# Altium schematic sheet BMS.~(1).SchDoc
size A3; SheetNumber: 3; SheetTotal: 3
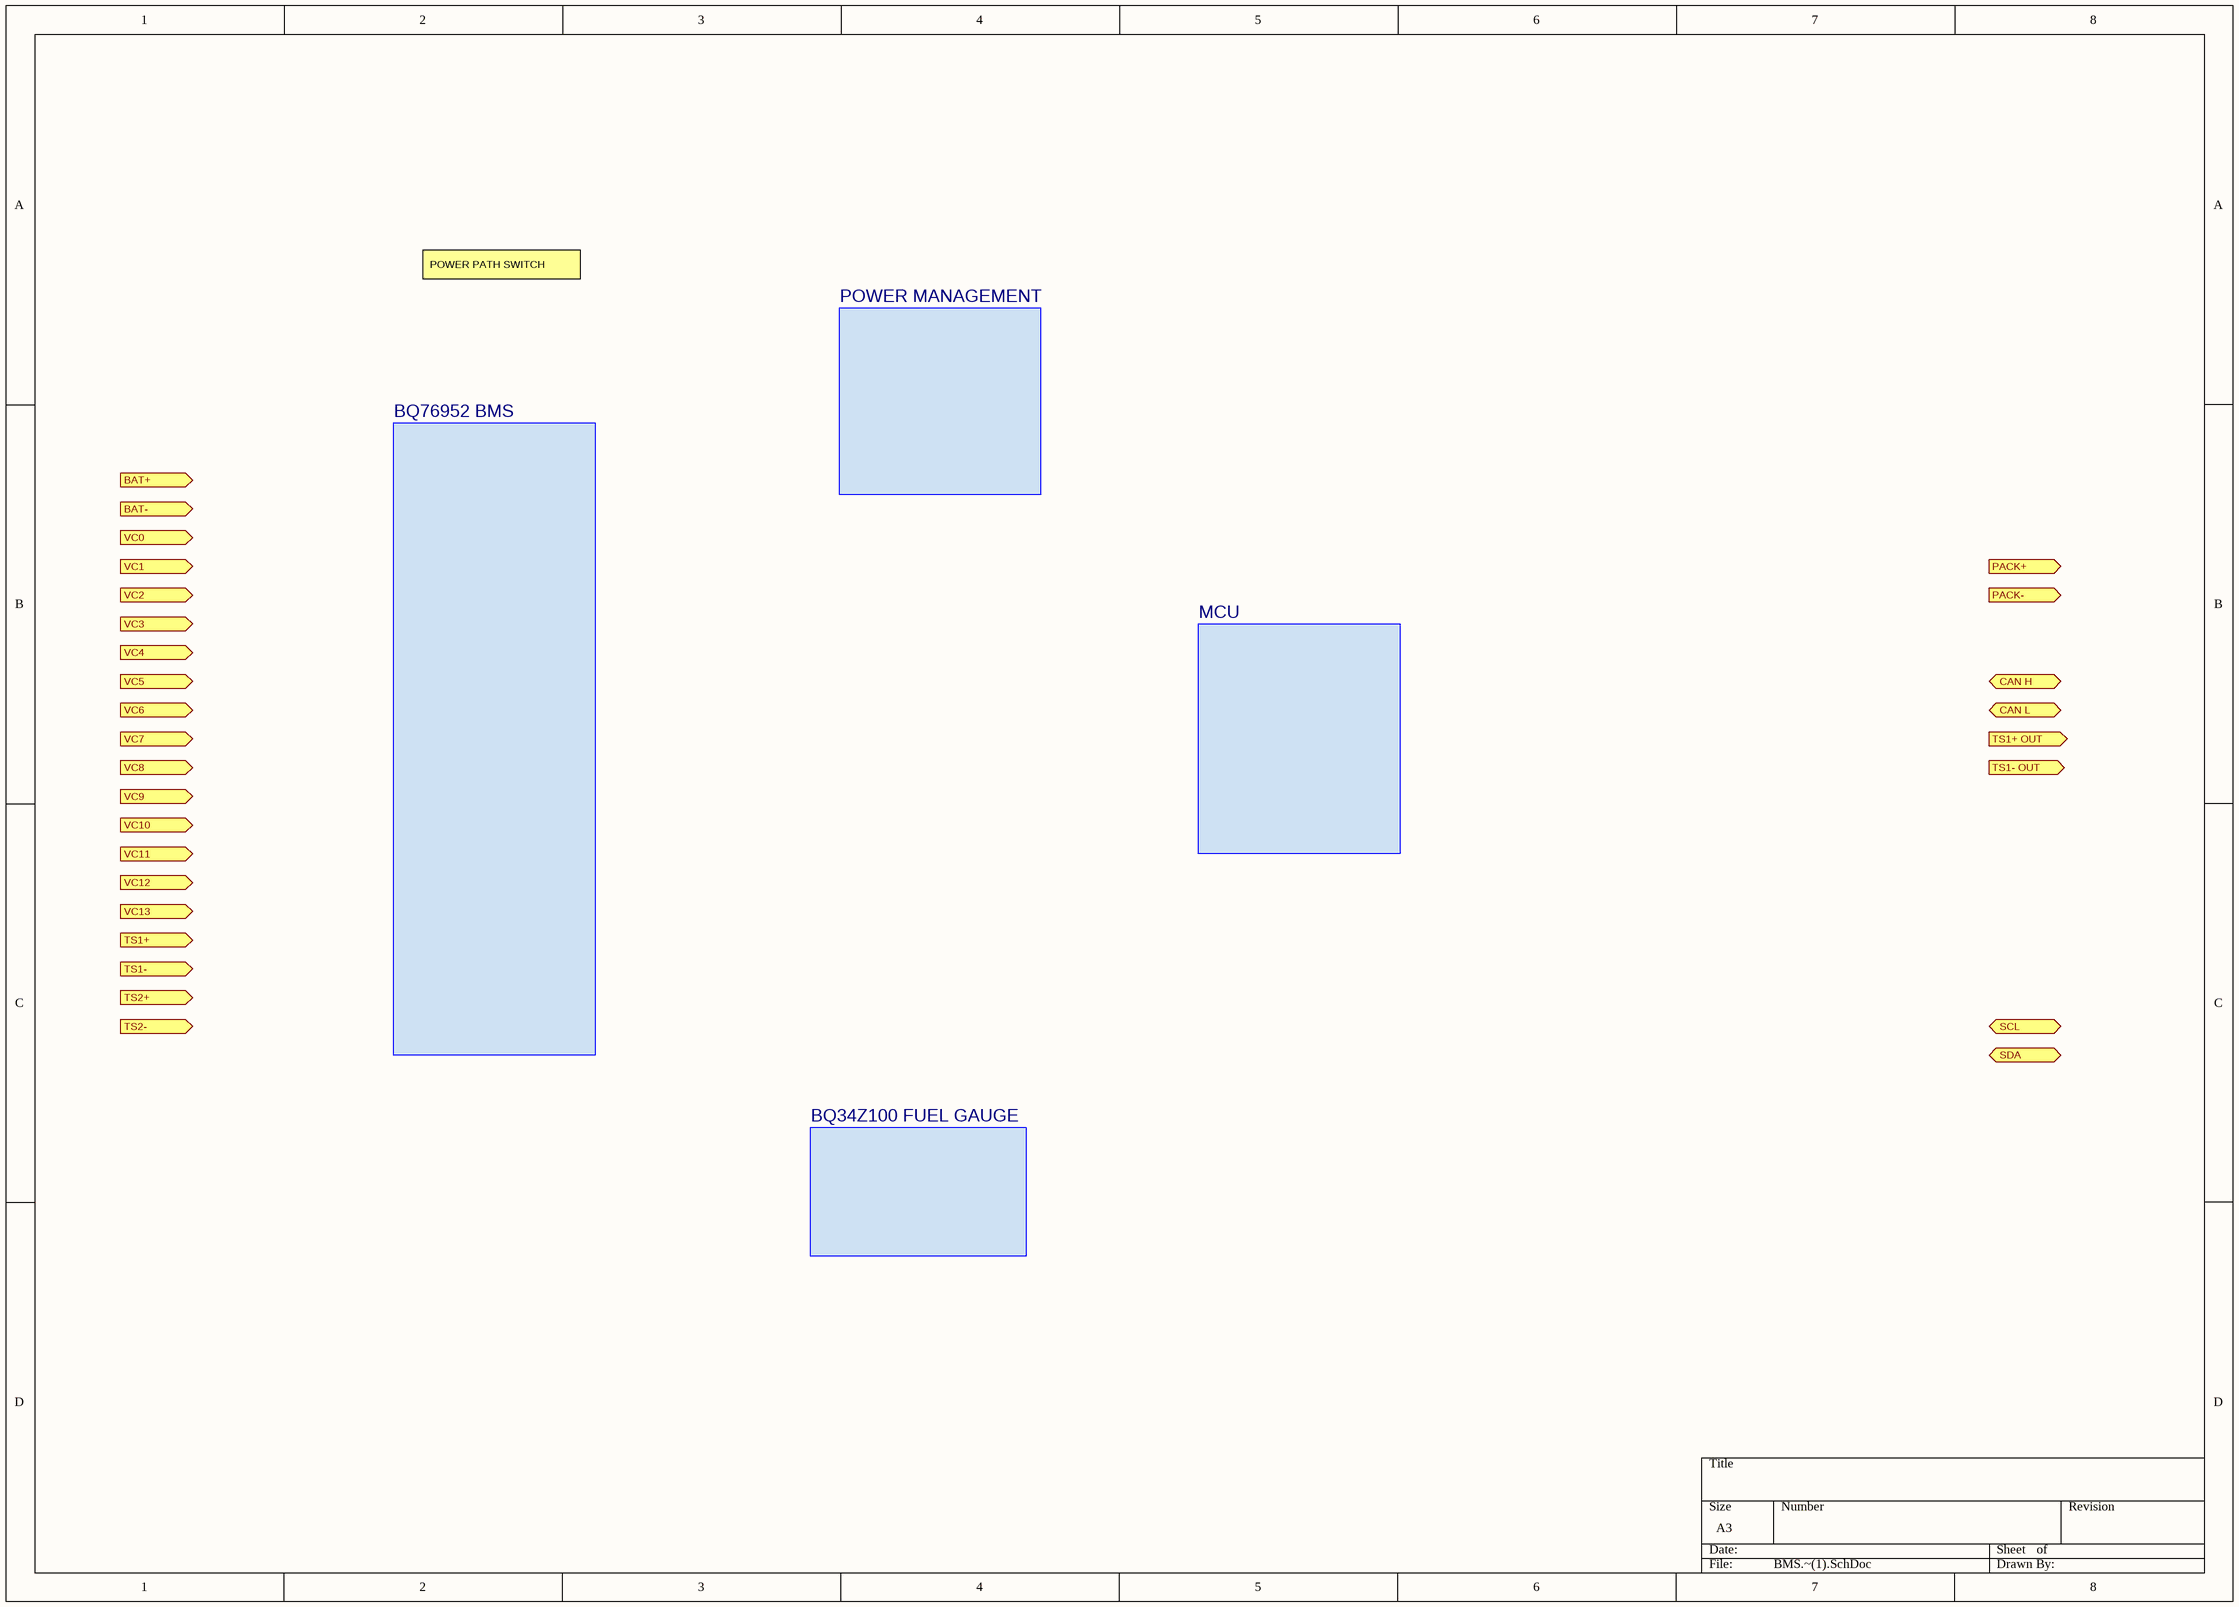
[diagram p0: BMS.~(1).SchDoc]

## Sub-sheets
BQ34Z100 FUEL GAUGE = BQ34Z100 FUEL GAUGE.SchDoc: no entries
BQ76952 BMS = BQ76952 BMS.SchDoc: no entries
MCU = MCU.SchDoc: no entries
POWER MANAGEMENT = POWER MANAGEMENT.SchDoc: no entries

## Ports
BAT+ (in, see Arhitecture[3B]), BAT- (in, see Arhitecture[3C]), CAN H (bidir, see Arhitecture[4B]), CAN L (bidir, see Arhitecture[4B]), PACK+ (out, see Arhitecture[4C], CHARGER[1B]), PACK- (out, see Arhitecture[4C], CHARGER[1C]), SCL (bidir, see Arhitecture[4C], CHARGER[1D]), SDA (bidir, see Arhitecture[4C], CHARGER[1D]), TS1+ (in, see Arhitecture[3C]), TS1+ OUT (out, see Arhitecture[4C]), TS1- (in, see Arhitecture[3C]), TS1- OUT (out, see Arhitecture[4C]), TS2+ (in, see Arhitecture[3C]), TS2- (in, see Arhitecture[3C]), VC0 (in, see Arhitecture[3C]), VC1 (in, see Arhitecture[3C]), VC2 (in, see Arhitecture[3C]), VC3 (in, see Arhitecture[3C]), VC4 (in, see Arhitecture[3C]), VC5 (in, see Arhitecture[3C]), VC6 (in, see Arhitecture[3B]), VC7 (in, see Arhitecture[3B]), VC8 (in, see Arhitecture[3B]), VC9 (in, see Arhitecture[3B]), VC10 (in, see Arhitecture[3B]), VC11 (in, see Arhitecture[3B]), VC12 (in, see Arhitecture[3B]), VC13 (in, see Arhitecture[3B])

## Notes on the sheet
- POWER PATH SWITCH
